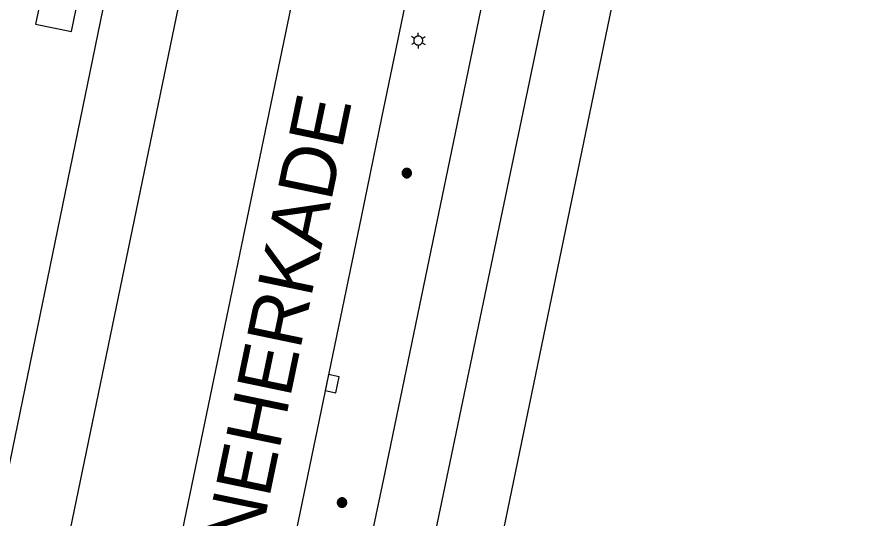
# Model space of a CAD drawing. Extents: x 81065 to 81486, y 452384 to 452681.
# Drawn here: x 81233.14 to 81256.39, y 452560.19 to 452573.86 of the extents above; entities that cross this region are included whole.
import ezdxf

# ---------------------------------------------------------------- set-up
doc = ezdxf.new("R2010")
doc.units = 0
for name, color, linetype in [('B-BH-AL-TOPOGRAFIE_STRAATNAAM-S', 7, 'Continuous'), ('B-BH-GR-BOOM-S', 7, 'Continuous'), ('B-BH-IE-MEUBILAIR_WEGMEUBILAIR_LICHTMAST-S', 7, 'Continuous'), ('B-BH-VH-KANTOPSLUITING-GV', 7, 'Continuous'), ('B-SRI-KOLK_COMBINATIE-S', 7, 'Continuous'), ('B-WE-VW-MARKERING_LANGS_STREEP_13_010-G', 7, 'Continuous'), ('B-WE-VW-MARKERING_LANGS_STREEP_30270_010-G', 7, 'Continuous'), ('N-OI-KL-VRI_LUS_DETECTIE-G', 7, 'Continuous')]:
    doc.layers.add(name, color=color, linetype=linetype)

msp = doc.modelspace()

# ---------------------------------------------------------------- linework, layer by layer
at = {"layer": 'B-BH-GR-BOOM-S'}
for points in [[(81243.623, 452569.608), (81243.624, 452569.594), (81243.626, 452569.581), (81243.629, 452569.568), (81243.634, 452569.556), (81243.64, 452569.544), (81243.648, 452569.532), (81243.656, 452569.522), (81243.666, 452569.512), (81243.676, 452569.504), (81243.688, 452569.496), (81243.7, 452569.49), (81243.712, 452569.485), (81243.725, 452569.482), (81243.738, 452569.48), (81243.752, 452569.479), (81243.765, 452569.48), (81243.779, 452569.482), (81243.792, 452569.485), (81243.804, 452569.49), (81243.816, 452569.496), (81243.828, 452569.504), (81243.838, 452569.512), (81243.848, 452569.522), (81243.856, 452569.532), (81243.864, 452569.544), (81243.87, 452569.556), (81243.874, 452569.568), (81243.878, 452569.581), (81243.88, 452569.594), (81243.881, 452569.608), (81243.88, 452569.621), (81243.878, 452569.635), (81243.874, 452569.648), (81243.87, 452569.66), (81243.864, 452569.672), (81243.856, 452569.684), (81243.848, 452569.694), (81243.838, 452569.704), (81243.828, 452569.712), (81243.816, 452569.72), (81243.804, 452569.726), (81243.792, 452569.73), (81243.779, 452569.734), (81243.765, 452569.736), (81243.752, 452569.737), (81243.738, 452569.736), (81243.725, 452569.734), (81243.712, 452569.73), (81243.7, 452569.726), (81243.688, 452569.72), (81243.676, 452569.712), (81243.666, 452569.704), (81243.656, 452569.694), (81243.648, 452569.684), (81243.64, 452569.672), (81243.634, 452569.66), (81243.629, 452569.648), (81243.626, 452569.635), (81243.624, 452569.621), (81243.623, 452569.608)], [(81243.648, 452569.608), (81243.648, 452569.597), (81243.65, 452569.586), (81243.653, 452569.576), (81243.657, 452569.565), (81243.661, 452569.556), (81243.667, 452569.547), (81243.674, 452569.538), (81243.682, 452569.53), (81243.691, 452569.523), (81243.7, 452569.517), (81243.709, 452569.513), (81243.72, 452569.509), (81243.73, 452569.506), (81243.741, 452569.504), (81243.752, 452569.504), (81243.763, 452569.504), (81243.774, 452569.506), (81243.784, 452569.509), (81243.794, 452569.513), (81243.804, 452569.517), (81243.813, 452569.523), (81243.822, 452569.53), (81243.83, 452569.538), (81243.836, 452569.547), (81243.842, 452569.556), (81243.847, 452569.565), (81243.851, 452569.576), (81243.854, 452569.586), (81243.856, 452569.597), (81243.856, 452569.608), (81243.856, 452569.619), (81243.854, 452569.63), (81243.851, 452569.64), (81243.847, 452569.65), (81243.842, 452569.66), (81243.836, 452569.669), (81243.83, 452569.678), (81243.822, 452569.686), (81243.813, 452569.692), (81243.804, 452569.698), (81243.794, 452569.703), (81243.784, 452569.707), (81243.774, 452569.71), (81243.763, 452569.712), (81243.752, 452569.712), (81243.741, 452569.712), (81243.73, 452569.71), (81243.72, 452569.707), (81243.709, 452569.703), (81243.7, 452569.698), (81243.691, 452569.692), (81243.682, 452569.686), (81243.674, 452569.678), (81243.667, 452569.669), (81243.661, 452569.66), (81243.657, 452569.65), (81243.653, 452569.64), (81243.65, 452569.63), (81243.648, 452569.619), (81243.648, 452569.608)], [(81243.67, 452569.608), (81243.671, 452569.599), (81243.672, 452569.591), (81243.674, 452569.583), (81243.677, 452569.575), (81243.681, 452569.567), (81243.686, 452569.56), (81243.691, 452569.553), (81243.697, 452569.547), (81243.704, 452569.542), (81243.711, 452569.537), (81243.719, 452569.533), (81243.727, 452569.53), (81243.735, 452569.528), (81243.743, 452569.527), (81243.752, 452569.526), (81243.76, 452569.527), (81243.769, 452569.528), (81243.777, 452569.53), (81243.785, 452569.533), (81243.793, 452569.537), (81243.8, 452569.542), (81243.807, 452569.547), (81243.813, 452569.553), (81243.818, 452569.56), (81243.823, 452569.567), (81243.826, 452569.575), (81243.83, 452569.583), (81243.832, 452569.591), (81243.833, 452569.599), (81243.834, 452569.608), (81243.833, 452569.616), (81243.832, 452569.625), (81243.83, 452569.633), (81243.826, 452569.641), (81243.823, 452569.649), (81243.818, 452569.656), (81243.813, 452569.663), (81243.807, 452569.669), (81243.8, 452569.674), (81243.793, 452569.679), (81243.785, 452569.682), (81243.777, 452569.686), (81243.769, 452569.688), (81243.76, 452569.689), (81243.752, 452569.69), (81243.743, 452569.689), (81243.735, 452569.688), (81243.727, 452569.686), (81243.719, 452569.682), (81243.711, 452569.679), (81243.704, 452569.674), (81243.697, 452569.669), (81243.691, 452569.663), (81243.686, 452569.656), (81243.681, 452569.649), (81243.677, 452569.641), (81243.674, 452569.633), (81243.672, 452569.625), (81243.671, 452569.616), (81243.67, 452569.608)], [(81243.693, 452569.608), (81243.694, 452569.602), (81243.695, 452569.596), (81243.696, 452569.59), (81243.698, 452569.584), (81243.701, 452569.579), (81243.705, 452569.573), (81243.708, 452569.569), (81243.713, 452569.564), (81243.717, 452569.561), (81243.723, 452569.557), (81243.728, 452569.554), (81243.734, 452569.552), (81243.74, 452569.551), (81243.746, 452569.55), (81243.752, 452569.549), (81243.758, 452569.55), (81243.764, 452569.551), (81243.77, 452569.552), (81243.776, 452569.554), (81243.781, 452569.557), (81243.786, 452569.561), (81243.791, 452569.564), (81243.796, 452569.569), (81243.799, 452569.573), (81243.803, 452569.579), (81243.806, 452569.584), (81243.808, 452569.59), (81243.809, 452569.596), (81243.81, 452569.602), (81243.811, 452569.608), (81243.81, 452569.614), (81243.809, 452569.62), (81243.808, 452569.626), (81243.806, 452569.632), (81243.803, 452569.637), (81243.799, 452569.642), (81243.796, 452569.647), (81243.791, 452569.652), (81243.786, 452569.655), (81243.781, 452569.659), (81243.776, 452569.662), (81243.77, 452569.664), (81243.764, 452569.665), (81243.758, 452569.666), (81243.752, 452569.667), (81243.746, 452569.666), (81243.74, 452569.665), (81243.734, 452569.664), (81243.728, 452569.662), (81243.723, 452569.659), (81243.717, 452569.655), (81243.713, 452569.652), (81243.708, 452569.647), (81243.705, 452569.642), (81243.701, 452569.637), (81243.698, 452569.632), (81243.696, 452569.626), (81243.695, 452569.62), (81243.694, 452569.614), (81243.693, 452569.608)], [(81243.716, 452569.608), (81243.716, 452569.604), (81243.717, 452569.601), (81243.718, 452569.597), (81243.719, 452569.593), (81243.721, 452569.59), (81243.723, 452569.587), (81243.725, 452569.584), (81243.728, 452569.581), (81243.731, 452569.579), (81243.734, 452569.577), (81243.737, 452569.575), (81243.741, 452569.574), (81243.745, 452569.573), (81243.748, 452569.572), (81243.752, 452569.572), (81243.756, 452569.572), (81243.759, 452569.573), (81243.763, 452569.574), (81243.767, 452569.575), (81243.77, 452569.577), (81243.773, 452569.579), (81243.776, 452569.581), (81243.778, 452569.584), (81243.781, 452569.587), (81243.783, 452569.59), (81243.785, 452569.593), (81243.786, 452569.597), (81243.787, 452569.601), (81243.788, 452569.604), (81243.788, 452569.608), (81243.788, 452569.612), (81243.787, 452569.615), (81243.786, 452569.619), (81243.785, 452569.623), (81243.783, 452569.626), (81243.781, 452569.629), (81243.778, 452569.632), (81243.776, 452569.634), (81243.773, 452569.637), (81243.77, 452569.639), (81243.767, 452569.641), (81243.763, 452569.642), (81243.759, 452569.643), (81243.756, 452569.644), (81243.752, 452569.644), (81243.748, 452569.644), (81243.745, 452569.643), (81243.741, 452569.642), (81243.737, 452569.641), (81243.734, 452569.639), (81243.731, 452569.637), (81243.728, 452569.634), (81243.725, 452569.632), (81243.723, 452569.629), (81243.721, 452569.626), (81243.719, 452569.623), (81243.718, 452569.619), (81243.717, 452569.615), (81243.716, 452569.612), (81243.716, 452569.608)], [(81243.739, 452569.608), (81243.739, 452569.607), (81243.739, 452569.605), (81243.74, 452569.604), (81243.74, 452569.603), (81243.741, 452569.602), (81243.742, 452569.6), (81243.742, 452569.599), (81243.743, 452569.598), (81243.744, 452569.598), (81243.746, 452569.597), (81243.747, 452569.596), (81243.748, 452569.596), (81243.749, 452569.595), (81243.751, 452569.595), (81243.752, 452569.595), (81243.753, 452569.595), (81243.755, 452569.595), (81243.756, 452569.596), (81243.757, 452569.596), (81243.758, 452569.597), (81243.76, 452569.598), (81243.761, 452569.598), (81243.762, 452569.599), (81243.762, 452569.6), (81243.763, 452569.602), (81243.764, 452569.603), (81243.764, 452569.604), (81243.765, 452569.605), (81243.765, 452569.607), (81243.765, 452569.608), (81243.765, 452569.609), (81243.765, 452569.611), (81243.764, 452569.612), (81243.764, 452569.613), (81243.763, 452569.614), (81243.762, 452569.616), (81243.762, 452569.617), (81243.761, 452569.618), (81243.76, 452569.618), (81243.758, 452569.619), (81243.757, 452569.62), (81243.756, 452569.62), (81243.755, 452569.621), (81243.753, 452569.621), (81243.752, 452569.621), (81243.751, 452569.621), (81243.749, 452569.621), (81243.748, 452569.62), (81243.747, 452569.62), (81243.746, 452569.619), (81243.744, 452569.618), (81243.743, 452569.618), (81243.742, 452569.617), (81243.742, 452569.616), (81243.741, 452569.614), (81243.74, 452569.613), (81243.74, 452569.612), (81243.739, 452569.611), (81243.739, 452569.609), (81243.739, 452569.608)], [(81241.858, 452560.633), (81241.859, 452560.619), (81241.861, 452560.606), (81241.864, 452560.593), (81241.869, 452560.581), (81241.875, 452560.569), (81241.883, 452560.557), (81241.891, 452560.547), (81241.901, 452560.537), (81241.911, 452560.529), (81241.923, 452560.521), (81241.935, 452560.515), (81241.947, 452560.51), (81241.96, 452560.507), (81241.973, 452560.505), (81241.987, 452560.504), (81242, 452560.505), (81242.014, 452560.507), (81242.027, 452560.51), (81242.039, 452560.515), (81242.051, 452560.521), (81242.063, 452560.529), (81242.073, 452560.537), (81242.083, 452560.547), (81242.091, 452560.557), (81242.099, 452560.569), (81242.105, 452560.581), (81242.109, 452560.593), (81242.113, 452560.606), (81242.115, 452560.619), (81242.116, 452560.633), (81242.115, 452560.646), (81242.113, 452560.66), (81242.109, 452560.673), (81242.105, 452560.685), (81242.099, 452560.697), (81242.091, 452560.709), (81242.083, 452560.719), (81242.073, 452560.729), (81242.063, 452560.737), (81242.051, 452560.745), (81242.039, 452560.751), (81242.027, 452560.755), (81242.014, 452560.759), (81242, 452560.761), (81241.987, 452560.762), (81241.973, 452560.761), (81241.96, 452560.759), (81241.947, 452560.755), (81241.935, 452560.751), (81241.923, 452560.745), (81241.911, 452560.737), (81241.901, 452560.729), (81241.891, 452560.719), (81241.883, 452560.709), (81241.875, 452560.697), (81241.869, 452560.685), (81241.864, 452560.673), (81241.861, 452560.66), (81241.859, 452560.646), (81241.858, 452560.633)], [(81241.883, 452560.633), (81241.883, 452560.622), (81241.885, 452560.611), (81241.888, 452560.601), (81241.892, 452560.59), (81241.896, 452560.581), (81241.902, 452560.572), (81241.909, 452560.563), (81241.917, 452560.555), (81241.926, 452560.548), (81241.935, 452560.542), (81241.944, 452560.538), (81241.955, 452560.534), (81241.965, 452560.531), (81241.976, 452560.529), (81241.987, 452560.529), (81241.998, 452560.529), (81242.009, 452560.531), (81242.019, 452560.534), (81242.029, 452560.538), (81242.039, 452560.542), (81242.048, 452560.548), (81242.057, 452560.555), (81242.065, 452560.563), (81242.071, 452560.572), (81242.077, 452560.581), (81242.082, 452560.59), (81242.086, 452560.601), (81242.089, 452560.611), (81242.091, 452560.622), (81242.091, 452560.633), (81242.091, 452560.644), (81242.089, 452560.655), (81242.086, 452560.665), (81242.082, 452560.675), (81242.077, 452560.685), (81242.071, 452560.694), (81242.065, 452560.703), (81242.057, 452560.711), (81242.048, 452560.717), (81242.039, 452560.723), (81242.029, 452560.728), (81242.019, 452560.732), (81242.009, 452560.735), (81241.998, 452560.737), (81241.987, 452560.737), (81241.976, 452560.737), (81241.965, 452560.735), (81241.955, 452560.732), (81241.944, 452560.728), (81241.935, 452560.723), (81241.926, 452560.717), (81241.917, 452560.711), (81241.909, 452560.703), (81241.902, 452560.694), (81241.896, 452560.685), (81241.892, 452560.675), (81241.888, 452560.665), (81241.885, 452560.655), (81241.883, 452560.644), (81241.883, 452560.633)], [(81241.905, 452560.633), (81241.906, 452560.624), (81241.907, 452560.616), (81241.909, 452560.608), (81241.912, 452560.6), (81241.916, 452560.592), (81241.921, 452560.585), (81241.926, 452560.578), (81241.932, 452560.572), (81241.939, 452560.567), (81241.946, 452560.562), (81241.954, 452560.558), (81241.962, 452560.555), (81241.97, 452560.553), (81241.978, 452560.552), (81241.987, 452560.551), (81241.995, 452560.552), (81242.004, 452560.553), (81242.012, 452560.555), (81242.02, 452560.558), (81242.028, 452560.562), (81242.035, 452560.567), (81242.042, 452560.572), (81242.048, 452560.578), (81242.053, 452560.585), (81242.058, 452560.592), (81242.061, 452560.6), (81242.065, 452560.608), (81242.067, 452560.616), (81242.068, 452560.624), (81242.069, 452560.633), (81242.068, 452560.641), (81242.067, 452560.65), (81242.065, 452560.658), (81242.061, 452560.666), (81242.058, 452560.674), (81242.053, 452560.681), (81242.048, 452560.688), (81242.042, 452560.694), (81242.035, 452560.699), (81242.028, 452560.704), (81242.02, 452560.707), (81242.012, 452560.711), (81242.004, 452560.713), (81241.995, 452560.714), (81241.987, 452560.715), (81241.978, 452560.714), (81241.97, 452560.713), (81241.962, 452560.711), (81241.954, 452560.707), (81241.946, 452560.704), (81241.939, 452560.699), (81241.932, 452560.694), (81241.926, 452560.688), (81241.921, 452560.681), (81241.916, 452560.674), (81241.912, 452560.666), (81241.909, 452560.658), (81241.907, 452560.65), (81241.906, 452560.641), (81241.905, 452560.633)], [(81241.928, 452560.633), (81241.929, 452560.627), (81241.93, 452560.621), (81241.931, 452560.615), (81241.933, 452560.609), (81241.936, 452560.604), (81241.94, 452560.598), (81241.943, 452560.594), (81241.948, 452560.589), (81241.952, 452560.586), (81241.958, 452560.582), (81241.963, 452560.579), (81241.969, 452560.577), (81241.975, 452560.576), (81241.981, 452560.575), (81241.987, 452560.574), (81241.993, 452560.575), (81241.999, 452560.576), (81242.005, 452560.577), (81242.011, 452560.579), (81242.016, 452560.582), (81242.021, 452560.586), (81242.026, 452560.589), (81242.031, 452560.594), (81242.034, 452560.598), (81242.038, 452560.604), (81242.041, 452560.609), (81242.043, 452560.615), (81242.044, 452560.621), (81242.045, 452560.627), (81242.046, 452560.633), (81242.045, 452560.639), (81242.044, 452560.645), (81242.043, 452560.651), (81242.041, 452560.657), (81242.038, 452560.662), (81242.034, 452560.667), (81242.031, 452560.672), (81242.026, 452560.677), (81242.021, 452560.68), (81242.016, 452560.684), (81242.011, 452560.687), (81242.005, 452560.689), (81241.999, 452560.69), (81241.993, 452560.691), (81241.987, 452560.692), (81241.981, 452560.691), (81241.975, 452560.69), (81241.969, 452560.689), (81241.963, 452560.687), (81241.958, 452560.684), (81241.952, 452560.68), (81241.948, 452560.677), (81241.943, 452560.672), (81241.94, 452560.667), (81241.936, 452560.662), (81241.933, 452560.657), (81241.931, 452560.651), (81241.93, 452560.645), (81241.929, 452560.639), (81241.928, 452560.633)], [(81241.951, 452560.633), (81241.951, 452560.629), (81241.952, 452560.626), (81241.953, 452560.622), (81241.954, 452560.618), (81241.956, 452560.615), (81241.958, 452560.612), (81241.96, 452560.609), (81241.963, 452560.606), (81241.966, 452560.604), (81241.969, 452560.602), (81241.972, 452560.6), (81241.976, 452560.599), (81241.98, 452560.598), (81241.983, 452560.597), (81241.987, 452560.597), (81241.991, 452560.597), (81241.994, 452560.598), (81241.998, 452560.599), (81242.002, 452560.6), (81242.005, 452560.602), (81242.008, 452560.604), (81242.011, 452560.606), (81242.013, 452560.609), (81242.016, 452560.612), (81242.018, 452560.615), (81242.02, 452560.618), (81242.021, 452560.622), (81242.022, 452560.626), (81242.023, 452560.629), (81242.023, 452560.633), (81242.023, 452560.637), (81242.022, 452560.64), (81242.021, 452560.644), (81242.02, 452560.648), (81242.018, 452560.651), (81242.016, 452560.654), (81242.013, 452560.657), (81242.011, 452560.659), (81242.008, 452560.662), (81242.005, 452560.664), (81242.002, 452560.666), (81241.998, 452560.667), (81241.994, 452560.668), (81241.991, 452560.669), (81241.987, 452560.669), (81241.983, 452560.669), (81241.98, 452560.668), (81241.976, 452560.667), (81241.972, 452560.666), (81241.969, 452560.664), (81241.966, 452560.662), (81241.963, 452560.659), (81241.96, 452560.657), (81241.958, 452560.654), (81241.956, 452560.651), (81241.954, 452560.648), (81241.953, 452560.644), (81241.952, 452560.64), (81241.951, 452560.637), (81241.951, 452560.633)], [(81241.974, 452560.633), (81241.974, 452560.632), (81241.974, 452560.63), (81241.975, 452560.629), (81241.975, 452560.628), (81241.976, 452560.627), (81241.977, 452560.625), (81241.977, 452560.624), (81241.978, 452560.623), (81241.979, 452560.623), (81241.981, 452560.622), (81241.982, 452560.621), (81241.983, 452560.621), (81241.984, 452560.62), (81241.986, 452560.62), (81241.987, 452560.62), (81241.988, 452560.62), (81241.99, 452560.62), (81241.991, 452560.621), (81241.992, 452560.621), (81241.993, 452560.622), (81241.995, 452560.623), (81241.996, 452560.623), (81241.997, 452560.624), (81241.997, 452560.625), (81241.998, 452560.627), (81241.999, 452560.628), (81241.999, 452560.629), (81242, 452560.63), (81242, 452560.632), (81242, 452560.633), (81242, 452560.634), (81242, 452560.636), (81241.999, 452560.637), (81241.999, 452560.638), (81241.998, 452560.639), (81241.997, 452560.641), (81241.997, 452560.642), (81241.996, 452560.643), (81241.995, 452560.643), (81241.993, 452560.644), (81241.992, 452560.645), (81241.991, 452560.645), (81241.99, 452560.646), (81241.988, 452560.646), (81241.987, 452560.646), (81241.986, 452560.646), (81241.984, 452560.646), (81241.983, 452560.645), (81241.982, 452560.645), (81241.981, 452560.644), (81241.979, 452560.643), (81241.978, 452560.643), (81241.977, 452560.642), (81241.977, 452560.641), (81241.976, 452560.639), (81241.975, 452560.638), (81241.975, 452560.637), (81241.974, 452560.636), (81241.974, 452560.634), (81241.974, 452560.633)]]:
    msp.add_lwpolyline(points, dxfattribs=at)
at = {"layer": 'B-BH-IE-MEUBILAIR_WEGMEUBILAIR_LICHTMAST-S'}
for p, q in [((81244.063, 452573.339), (81244.063, 452573.431)), ((81243.957, 452573.278), (81243.878, 452573.324)), ((81243.957, 452573.156), (81243.878, 452573.11)), ((81244.168, 452573.278), (81244.248, 452573.324)), ((81244.168, 452573.156), (81244.248, 452573.11)), ((81244.063, 452573.095), (81244.063, 452573.003))]:
    msp.add_line(p, q, dxfattribs=at)
msp.add_lwpolyline([(81243.941, 452573.217), (81243.942, 452573.204), (81243.943, 452573.191), (81243.947, 452573.179), (81243.951, 452573.167), (81243.957, 452573.156), (81243.964, 452573.145), (81243.972, 452573.135), (81243.981, 452573.126), (81243.991, 452573.118), (81244.002, 452573.111), (81244.013, 452573.105), (81244.025, 452573.101), (81244.038, 452573.097), (81244.05, 452573.096), (81244.063, 452573.095), (81244.076, 452573.096), (81244.088, 452573.097), (81244.101, 452573.101), (81244.113, 452573.105), (81244.124, 452573.111), (81244.135, 452573.118), (81244.145, 452573.126), (81244.154, 452573.135), (81244.162, 452573.145), (81244.169, 452573.156), (81244.174, 452573.167), (81244.179, 452573.179), (81244.182, 452573.191), (81244.184, 452573.204), (81244.185, 452573.217), (81244.184, 452573.23), (81244.182, 452573.242), (81244.179, 452573.255), (81244.174, 452573.267), (81244.169, 452573.278), (81244.162, 452573.289), (81244.154, 452573.299), (81244.145, 452573.308), (81244.135, 452573.316), (81244.124, 452573.323), (81244.113, 452573.328), (81244.101, 452573.333), (81244.088, 452573.336), (81244.076, 452573.338), (81244.063, 452573.339), (81244.05, 452573.338), (81244.037, 452573.336), (81244.025, 452573.333), (81244.013, 452573.328), (81244.002, 452573.323), (81243.991, 452573.316), (81243.981, 452573.308), (81243.972, 452573.299), (81243.964, 452573.289), (81243.957, 452573.278), (81243.951, 452573.267), (81243.947, 452573.255), (81243.943, 452573.242), (81243.942, 452573.23), (81243.941, 452573.217)], dxfattribs=at)
at = {"layer": 'B-BH-VH-KANTOPSLUITING-GV'}
for p, q in [((81246.695, 452618.418), (81232.053, 452547.692)), ((81230.235, 452548.568), (81237.12, 452582.041)), ((81250, 452577.378), (81242.428, 452540.786)), ((81244.316, 452577.158), (81243.065, 452571.111)), ((81245.074, 452570.691), (81246.329, 452576.74)), ((81243.065, 452571.111), (81242.515, 452568.452)), ((81244.521, 452568.028), (81245.074, 452570.691)), ((81242.515, 452568.452), (81241.155, 452561.875)), ((81243.158, 452561.455), (81244.521, 452568.028)), ((81241.155, 452561.875), (81240.671, 452559.538)), ((81242.676, 452559.132), (81243.158, 452561.455))]:
    msp.add_line(p, q, dxfattribs=at)
at = {"layer": 'B-SRI-KOLK_COMBINATIE-S'}
for p, q in [((81241.619, 452564.121), (81241.527, 452563.682)), ((81241.908, 452564.06), (81241.619, 452564.121)), ((81241.816, 452563.622), (81241.908, 452564.06)), ((81241.527, 452563.682), (81241.816, 452563.622))]:
    msp.add_line(p, q, dxfattribs=at)
at = {"layer": 'B-WE-VW-MARKERING_LANGS_STREEP_13_010-G'}
msp.add_line((81249.633, 452617.81), (81236.113, 452552.506), dxfattribs=at)
at = {"layer": 'B-WE-VW-MARKERING_LANGS_STREEP_30270_010-G'}
msp.add_line((81256.39, 452616.632), (81240.898, 452542.462), dxfattribs=at)
at = {"layer": 'N-OI-KL-VRI_LUS_DETECTIE-G'}
for p, q in [((81237.68, 452593.25), (81233.639, 452573.663)), ((81234.618, 452573.461), (81238.659, 452593.049)), ((81233.639, 452573.663), (81234.618, 452573.461))]:
    msp.add_line(p, q, dxfattribs=at)

# ---------------------------------------------------------------- texts
at = {"layer": 'B-BH-AL-TOPOGRAFIE_STRAATNAAM-S'}
msp.add_text('NEHERKADE', height=1.5, rotation=78.2165, dxfattribs=at).set_placement((81239.707, 452559.316))

doc.saveas('drawing.dxf')
